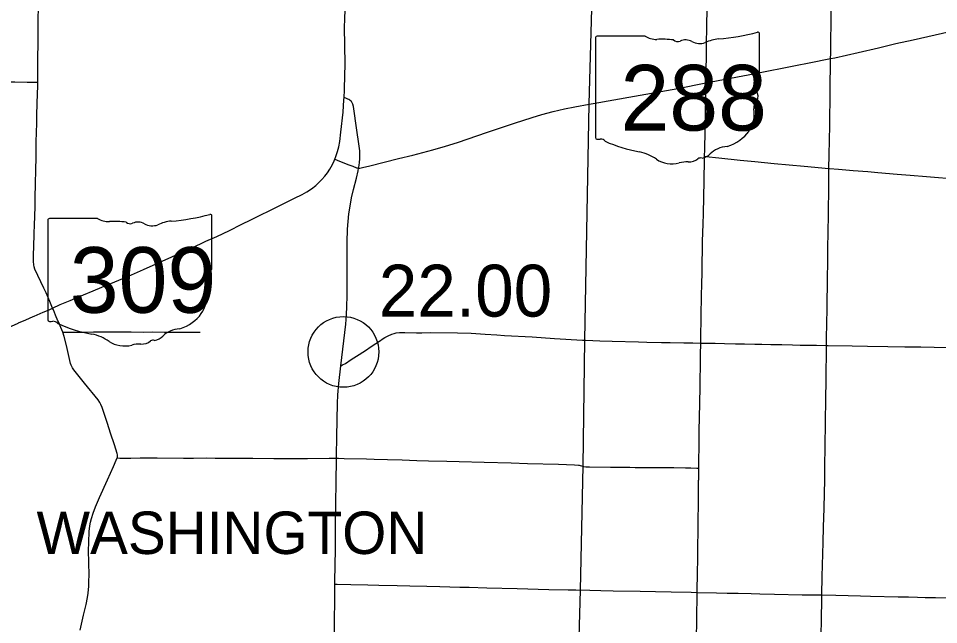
# Model space of a CAD drawing. Extents: x 1815539 to 1947826, y 273303 to 993194.
# Drawn here: x 1872474 to 1891996, y 966222 to 979080 of the extents above; entities that cross this region are included whole.
import ezdxf

# ---------------------------------------------------------------- set-up
doc = ezdxf.new("R2010")
doc.units = 0
for name, color, linetype in [('Default', 7, 'Continuous'), ('GM_X_County_Road', 7, 'Continuous'), ('GM_X_State_Route', 7, 'Continuous'), ('GM_X_Township', 7, 'Continuous'), ('GM_X_Township_Road', 7, 'Continuous'), ('GM_X_Township_Text', 7, 'Continuous'), ('SC_Shading3', 7, 'Continuous')]:
    doc.layers.add(name, color=color, linetype=linetype)

msp = doc.modelspace()

# ---------------------------------------------------------------- linework, layer by layer
at = {"layer": 'Default'}
msp.add_circle((1879369, 972005), 750, dxfattribs=at)
at = {"layer": 'GM_X_County_Road'}
for points in [[(1872883, 977728), (1872885, 977952), (1872887, 978231), (1872890, 978559), (1872895, 979018), (1872900, 979346), (1872916, 980444), (1872921, 980789), (1872925, 981002), (1872930, 981330), (1872932, 981494), (1872936, 981707), (1872938, 981870), (1872943, 982198), (1872947, 982477), (1872954, 982854), (1872958, 983018), (1872958, 983035), (1872959, 983067)], [(1887061, 977710), (1887063, 977813), (1887072, 978453), (1887082, 978978), (1887085, 979224), (1887088, 979339), (1887092, 979534), (1887093, 979696), (1887094, 979792), (1887097, 980100), (1887106, 980871), (1887117, 981642), (1887121, 982003), (1887131, 982544), (1887133, 982724), (1887133, 982742)], [(1889705, 978226), (1889707, 978335), (1889710, 978646), (1889714, 978942), (1889719, 979221), (1889736, 980140), (1889740, 980484), (1889743, 980763), (1889745, 980993), (1889754, 981320), (1889760, 981599), (1889766, 982092), (1889775, 982670)], [(1889671, 975899), (1889674, 976185), (1889686, 976808), (1889696, 977530), (1889705, 978226)], [(1872832, 975375), (1872836, 975482), (1872839, 975662), (1872842, 975776), (1872844, 975874), (1872845, 975923), (1872846, 975942), (1872846, 975974), (1872847, 976021), (1872850, 976200), (1872854, 976461), (1872863, 976855), (1872867, 977018), (1872874, 977280), (1872883, 977657), (1872883, 977728)], [(1887031, 976151), (1887034, 976304), (1887056, 977420), (1887061, 977710)], [(1886950, 972193), (1886951, 972319), (1886959, 972729), (1886962, 972893), (1886966, 973073), (1886969, 973221), (1886972, 973418), (1886977, 973713), (1886991, 974352), (1886999, 974713), (1887006, 974943), (1887021, 975632), (1887030, 976091), (1887031, 976151)], [(1889618, 972143), (1889620, 972296), (1889629, 972919), (1889640, 973592), (1889644, 973887), (1889648, 974199), (1889658, 974905), (1889667, 975545), (1889671, 975899)], [(1889671, 975899), (1889680, 975899), (1889875, 975882), (1890185, 975857), (1890495, 975829), (1890708, 975811), (1891116, 975777), (1891394, 975752), (1891737, 975724), (1892424, 975669), (1892800, 975641), (1892996, 975625), (1893170, 975612)], [(1873200, 972935), (1873141, 973076), (1873061, 973256), (1873013, 973359), (1872951, 973493), (1872825, 973760), (1872808, 973807), (1872799, 973856), (1872795, 973922), (1872797, 974035), (1872797, 974070), (1872802, 974233), (1872811, 974511), (1872816, 974707), (1872821, 974871), (1872828, 975101), (1872832, 975375)], [(1873262, 972784), (1873217, 972895), (1873200, 972935)], [(1873329, 972626), (1873310, 972668), (1873262, 972784)], [(1873414, 972427), (1873374, 972525), (1873329, 972626)], [(1873498, 972111), (1873444, 972329), (1873415, 972423), (1873414, 972427)], [(1873592, 971723), (1873582, 971760), (1873567, 971821), (1873507, 972075), (1873498, 972111)], [(1886911, 969542), (1886913, 969744), (1886915, 969957), (1886920, 970335), (1886930, 970908), (1886936, 971269), (1886939, 971466), (1886943, 971663), (1886946, 971942), (1886950, 972193)], [(1889520, 966850), (1889528, 967242), (1889547, 967964), (1889557, 968292), (1889566, 968686), (1889573, 969014), (1889580, 969276), (1889586, 969572), (1889592, 969998), (1889606, 971016), (1889611, 971393), (1889618, 972143)], [(1874573, 969761), (1874576, 969771), (1874579, 969786), (1874579, 969801), (1874575, 969822), (1874568, 969848), (1874509, 970035), (1874428, 970285), (1874361, 970488), (1874249, 970830), (1874225, 970891), (1874202, 970933), (1874164, 970986), (1873875, 971343), (1873650, 971625), (1873621, 971666), (1873605, 971695), (1873592, 971723)], [(1873787, 966104), (1873814, 966232), (1873858, 966424), (1873909, 966648), (1873937, 966793), (1873951, 966890), (1873965, 967036), (1873971, 967151), (1873972, 967265), (1873967, 967544), (1873963, 967789), (1873967, 967970), (1873978, 968199), (1873989, 968314), (1874002, 968395), (1874022, 968475), (1874057, 968585), (1874111, 968722), (1874195, 968918), (1874362, 969293), (1874489, 969577), (1874550, 969711), (1874570, 969756), (1874573, 969761)], [(1874573, 969761), (1874584, 969760), (1874629, 969754), (1874713, 969754), (1874860, 969754), (1875057, 969756), (1875204, 969756), (1875417, 969757), (1875974, 969755), (1876187, 969755), (1876465, 969756), (1876645, 969755), (1876793, 969753), (1877038, 969751), (1877186, 969750), (1877448, 969749), (1877890, 969747), (1878250, 969746), (1878610, 969747), (1879069, 969749), (1879220, 969750)], [(1886873, 966904), (1886872, 966954), (1886878, 967295), (1886886, 967639), (1886890, 967918), (1886893, 968164), (1886896, 968377), (1886901, 968836), (1886904, 969033), (1886904, 969076), (1886906, 969218), (1886906, 969232), (1886906, 969248), (1886906, 969260), (1886906, 969267), (1886906, 969278), (1886908, 969300), (1886910, 969334), (1886910, 969515), (1886911, 969542)], [(1879189, 967078), (1879234, 967077), (1879529, 967070), (1879890, 967062), (1880119, 967057), (1880513, 967048), (1880775, 967042), (1881136, 967034), (1881415, 967028), (1881628, 967022), (1881841, 967018), (1882038, 967012), (1882415, 967001), (1883055, 966984), (1883728, 966969), (1884138, 966960), (1884299, 966957)], [(1884299, 966957), (1884597, 966951), (1884827, 966945), (1885089, 966939), (1885663, 966928), (1885991, 966922), (1886320, 966917), (1886746, 966906), (1886873, 966904)], [(1886873, 966904), (1887281, 966896), (1887512, 966890), (1887742, 966885), (1888021, 966879), (1888202, 966876), (1888514, 966869), (1889105, 966856), (1889352, 966852), (1889499, 966850), (1889520, 966850)], [(1889424, 961538), (1889434, 962041), (1889441, 962402), (1889451, 963025), (1889459, 963534), (1889476, 964387), (1889485, 964945), (1889494, 965470), (1889503, 965962), (1889509, 966356), (1889517, 966733), (1889520, 966850)], [(1889520, 966850), (1889815, 966844), (1890339, 966831), (1890552, 966826), (1891142, 966812), (1891355, 966807), (1891551, 966803), (1891715, 966799), (1891830, 966797), (1891928, 966795), (1892240, 966789), (1892486, 966783), (1892912, 966776), (1893027, 966774), (1893240, 966769), (1893371, 966766), (1893551, 966761), (1893830, 966755), (1893978, 966753), (1894174, 966750), (1894502, 966742), (1894748, 966737)]]:
    msp.add_lwpolyline(points, dxfattribs=at)
at = {"layer": 'GM_X_State_Route'}
for points in [[(1879384, 977403), (1879392, 977559), (1879402, 977887), (1879403, 978084), (1879397, 978543), (1879395, 978855), (1879397, 979101), (1879405, 979231), (1879419, 979345), (1879443, 979474), (1879492, 979681), (1879595, 980078), (1879670, 980363), (1879762, 980712), (1879887, 981197)], [(1879690, 975904), (1879702, 975904), (1879719, 975906), (1879774, 975917), (1879933, 975955), (1880235, 976031), (1880538, 976106), (1880840, 976181), (1881269, 976294), (1881537, 976369), (1881787, 976449), (1882425, 976664), (1883000, 976858), (1883374, 976981), (1883579, 977042), (1883817, 977105), (1884057, 977161), (1884282, 977206), (1884583, 977260), (1884670, 977276), (1885543, 977430), (1886463, 977595), (1887061, 977710), (1887172, 977732), (1888107, 977913), (1888960, 978079), (1889250, 978135), (1889705, 978226), (1889797, 978245), (1890293, 978359), (1890725, 978458), (1891092, 978544), (1891460, 978628), (1891765, 978696), (1892388, 978840)], [(1876453, 974353), (1876683, 974457), (1876950, 974582), (1877201, 974705), (1877421, 974814), (1877995, 975098), (1878334, 975264), (1878495, 975346), (1878594, 975403), (1878690, 975467), (1878782, 975537), (1878844, 975591), (1878914, 975661), (1878978, 975735), (1879028, 975801), (1879082, 975883), (1879140, 975983), (1879175, 976058), (1879188, 976091), (1879211, 976150), (1879245, 976260), (1879269, 976356), (1879290, 976469), (1879316, 976664), (1879361, 977088), (1879380, 977349), (1879384, 977403)], [(1879690, 975904), (1879700, 975962), (1879709, 976031), (1879715, 976095), (1879717, 976174), (1879714, 976272), (1879699, 976418), (1879657, 976711), (1879582, 977213), (1879570, 977260), (1879556, 977289), (1879538, 977315), (1879522, 977333), (1879503, 977347), (1879485, 977358), (1879462, 977370), (1879436, 977382), (1879384, 977403)], [(1879188, 976091), (1879235, 976073), (1879465, 975984), (1879572, 975942), (1879648, 975912), (1879662, 975908), (1879679, 975905), (1879690, 975904)], [(1879178, 965960), (1879189, 967078), (1879189, 967141), (1879198, 967813), (1879201, 968256), (1879207, 968813), (1879213, 969224), (1879220, 969750), (1879220, 969798), (1879229, 970208), (1879243, 970913), (1879252, 971093), (1879274, 971338), (1879317, 971710), (1879417, 972593), (1879434, 972789), (1879442, 972969), (1879446, 973198), (1879448, 973641), (1879449, 973985), (1879451, 974330), (1879458, 974608), (1879468, 974772), (1879485, 974935), (1879509, 975098), (1879544, 975275), (1879585, 975451), (1879647, 975689), (1879681, 975849), (1879690, 975904)], [(1873856, 973217), (1874061, 973302), (1874242, 973380), (1874328, 973413), (1874435, 973456), (1874603, 973525), (1874875, 973639), (1875131, 973751), (1875459, 973900), (1875727, 974024), (1876087, 974185), (1876340, 974301), (1876453, 974353)], [(1871338, 972094), (1871654, 972249), (1871717, 972279), (1871817, 972327), (1871922, 972374), (1872146, 972475), (1872326, 972554), (1872469, 972616), (1872476, 972620), (1872631, 972687), (1872790, 972756), (1872807, 972764), (1873002, 972849), (1873123, 972901), (1873200, 972935), (1873363, 973008), (1873502, 973068), (1873573, 973099), (1873686, 973147), (1873708, 973156), (1873765, 973179), (1873807, 973197), (1873856, 973217)]]:
    msp.add_lwpolyline(points, dxfattribs=at)
at = {"layer": 'GM_X_Township'}
msp.add_lwpolyline([(1884254, 961672), (1884396, 966955), (1884454, 969588), (1884489, 972257), (1884586, 977269), (1884741, 982824), (1884889, 988110)], dxfattribs=at)
at = {"layer": 'GM_X_Township_Road'}
for points in [[(1869001, 977778), (1869250, 977773), (1869546, 977769), (1869972, 977762), (1870529, 977753), (1870709, 977751), (1871152, 977746), (1871743, 977739), (1872103, 977737), (1872399, 977733), (1872661, 977730), (1872775, 977729), (1872857, 977728), (1872883, 977728)], [(1887031, 976151), (1887055, 976148), (1887332, 976121), (1887789, 976075), (1888099, 976042), (1888507, 976004), (1889144, 975946), (1889671, 975899)], [(1873414, 972427), (1873446, 972427), (1873615, 972427)], [(1873615, 972427), (1873760, 972427)], [(1873760, 972427), (1873857, 972427), (1874066, 972431), (1874329, 972431), (1874723, 972429), (1874868, 972429), (1875129, 972426), (1875326, 972430), (1875572, 972427), (1875983, 972421), (1876164, 972421), (1876295, 972424), (1876328, 972425)], [(1879317, 971710), (1879353, 971731), (1879410, 971763), (1879534, 971844), (1879644, 971915), (1879837, 972039), (1879961, 972119), (1880153, 972245), (1880194, 972275), (1880249, 972311), (1880322, 972349), (1880396, 972381), (1880443, 972396), (1880491, 972407), (1880557, 972414), (1880671, 972415), (1880918, 972413), (1881032, 972413), (1881213, 972414), (1881787, 972410), (1882082, 972400), (1882377, 972383), (1882623, 972368), (1882786, 972357), (1883376, 972322), (1883851, 972292), (1884445, 972256)], [(1884445, 972256), (1884503, 972254)], [(1884503, 972254), (1884664, 972248), (1884811, 972242), (1885072, 972234), (1885628, 972218), (1885808, 972214), (1886119, 972207), (1886299, 972204), (1886593, 972199), (1886781, 972195), (1886950, 972193)], [(1886950, 972193), (1887259, 972190), (1887456, 972187), (1887685, 972180), (1887882, 972175), (1888095, 972170), (1888243, 972168), (1888440, 972166), (1888670, 972160), (1888899, 972156), (1889063, 972152), (1889408, 972146), (1889618, 972143)], [(1889618, 972143), (1889654, 972142), (1890163, 972136), (1890491, 972130), (1890917, 972121), (1891278, 972116), (1891623, 972111), (1891902, 972107), (1892591, 972095), (1893132, 972086), (1893584, 972080), (1893789, 972077), (1894018, 972071), (1894460, 972064), (1894558, 972062), (1894706, 972059), (1894818, 972056)], [(1879220, 969750), (1879267, 969749), (1879382, 969746), (1879858, 969736), (1880022, 969729), (1880301, 969721), (1880613, 969713), (1880925, 969704), (1881171, 969697), (1881565, 969686), (1881828, 969681), (1882353, 969669), (1882928, 969654), (1883273, 969641), (1883930, 969621), (1884275, 969611), (1884356, 969605), (1884372, 969602)], [(1884372, 969602), (1884443, 969583)], [(1884443, 969583), (1884461, 969578), (1884509, 969570), (1884591, 969566), (1885034, 969563), (1885444, 969558), (1885559, 969557), (1885755, 969557), (1885903, 969556), (1886165, 969554), (1886378, 969551), (1886624, 969549), (1886739, 969546), (1886870, 969542), (1886886, 969542), (1886911, 969542)], [(1886785, 961597), (1886785, 961626), (1886789, 961756), (1886793, 961953), (1886797, 962182), (1886807, 962674), (1886811, 962985), (1886819, 963460), (1886826, 963852), (1886829, 964033), (1886828, 964697), (1886831, 964812), (1886842, 964956), (1886848, 965186), (1886852, 965497), (1886857, 965710), (1886859, 965923), (1886866, 966316), (1886870, 966513), (1886873, 966709), (1886874, 966824), (1886873, 966904)]]:
    msp.add_lwpolyline(points, dxfattribs=at)
at = {"layer": 'SC_Shading3'}
for p, q in [((1885769, 978701), (1884750, 978701)), ((1888196, 977648), (1888196, 978754)), ((1884716, 978665), (1884716, 976552)), ((1888196, 977648), (1888196, 977648)), ((1873100, 974800), (1873100, 972687)), ((1874154, 974836), (1873135, 974836)), ((1876581, 973783), (1876581, 974889)), ((1876580, 973783), (1876581, 973783))]:
    msp.add_line(p, q, dxfattribs=at)
for centre, major_axis, start_param, end_param in [((1884755, 978669), (40.3, 0), 1.712693, 3.28349), ((1886012, 978947), (391, 0), 4.042523, 4.731795), ((1886956, 981582), (3691, 0), 4.814394, 5.042369), ((1888157, 978758), (38.7, 0), 6.141152, 7.989035), ((1886141, 977515), (1404, 0), 1.404758, 1.657858), ((1886460, 978680), (113, 0), 3.836095, 5.185415), ((1886626, 978436), (235, 0), 0.950623, 2.079405), ((1886929, 978771), (282, 0), 4.081561, 5.145723), ((1887427, 978056), (743, 0), 1.699011, 2.107814), ((1888187, 977567), (60, 0), 1.883978, 3.671073), ((1887806, 977427), (360, 0), 5.934695, 6.695948), ((1888155, 977644), (41.5, 0), 5.05454, 6.418171), ((1888335, 977186), (262, 0), 2.387724, 3.262537), ((1887163, 977045), (923, 0), 5.101752, 6.440018), ((1884756, 976547), (40.7, 0), 3.00124, 4.508301), ((1884762, 976763), (310, 0), 4.665946, 4.897461), ((1884825, 976430), (112, 0), 0.519207, 1.627899), ((1886239, 978328), (2665, 0), 4.195997, 4.488961), ((1887552, 975958), (506, 0), 1.647645, 2.488434), ((1885444, 975602), (834, 0), 0.823519, 1.323587), ((1886912, 976347), (298, 0), 4.937069, 5.64225), ((1886346, 976419), (529, 0), 4.026481, 4.996735), ((1886652, 975689), (435, 0), 1.495662, 1.94098), ((1886690, 976261), (282, 0), 4.691044, 5.507374), ((1886945, 976056), (79.4, 0), 1.147584, 2.315152), ((1873140, 974804), (40.3, 0), 1.712693, 3.28349), ((1874397, 975082), (391, 0), 4.042523, 4.731795), ((1874526, 973650), (1404, 0), 1.404758, 1.657858), ((1875812, 974191), (743, 0), 1.699011, 2.107814), ((1875341, 977717), (3691, 0), 4.814394, 5.042369), ((1876542, 974893), (38.7, 0), 6.141152, 7.989035), ((1874845, 974815), (113, 0), 3.836095, 5.185415), ((1875011, 974571), (235, 0), 0.950623, 2.079405), ((1875313, 974906), (282, 0), 4.081561, 5.145723), ((1876572, 973702), (60, 0), 1.883978, 3.671073), ((1876190, 973562), (360, 0), 5.934695, 6.695948), ((1876539, 973779), (41.5, 0), 5.05454, 6.418171), ((1876720, 973321), (262, 0), 2.387724, 3.262537), ((1875548, 973180), (923, 0), 5.101752, 6.440018), ((1873141, 972682), (40.7, 0), 3.00124, 4.508301), ((1873147, 972898), (310, 0), 4.665946, 4.897461), ((1873210, 972565), (112, 0), 0.519207, 1.627899), ((1874623, 974463), (2665, 0), 4.195997, 4.488961), ((1875937, 972093), (506, 0), 1.647645, 2.488434), ((1873829, 971737), (834, 0), 0.823519, 1.323587), ((1875075, 972396), (282, 0), 4.691044, 5.507374), ((1875330, 972191), (79.4, 0), 1.147584, 2.315152), ((1875296, 972482), (298, 0), 4.937069, 5.64225), ((1874731, 972554), (529, 0), 4.026481, 4.996735), ((1875037, 971824), (435, 0), 1.495662, 1.94098)]:
    msp.add_ellipse(centre, major_axis=major_axis, ratio=0.8, start_param=start_param, end_param=end_param, dxfattribs=at)

# ---------------------------------------------------------------- texts
at = {"layer": 'Default'}
msp.add_text('22.00', height=1100, dxfattribs=at).set_placement((1880119, 972755))
at = {"layer": 'GM_X_Township_Text'}
msp.add_text('WASHINGTON', height=900, rotation=0, dxfattribs=at).set_placement((1872858, 967719))
at = {"layer": 'SC_Shading3'}
for s, p in [('288', (1885247, 976701)), ('309', (1873564, 972836))]:
    msp.add_text(s, height=1392.2, dxfattribs=at).set_placement(p)

doc.saveas('drawing.dxf')
